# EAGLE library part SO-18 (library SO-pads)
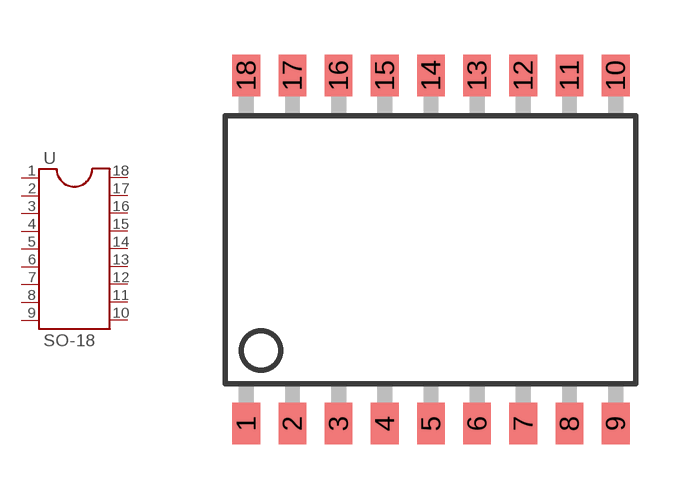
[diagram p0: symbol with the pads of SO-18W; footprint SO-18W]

Designator prefix -

## SO-18  [SO-18W]
1  1  pas
2  2  pas
3  3  pas
4  4  pas
5  5  pas
6  6  pas
7  7  pas
8  8  pas
9  9  pas
10  10  pas
11  11  pas
12  12  pas
13  13  pas
14  14  pas
15  15  pas
16  16  pas
17  17  pas
18  18  pas

## Footprint SO-18W (pad centres in mm)
smd 0.762 x 1.143: 1 -5.08,-4.788; 2 -3.81,-4.788; 3 -2.54,-4.788; 4 -1.27,-4.788; 5 0,-4.788; 6 1.27,-4.788; 7 2.54,-4.788; 8 3.81,-4.788; 9 5.08,-4.788; 10 5.08,4.788; 11 3.81,4.788; 12 2.54,4.788; 13 1.27,4.788; 14 0,4.788; 15 -1.27,4.788; 16 -2.54,4.788; 17 -3.81,4.788; 18 -5.08,4.788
